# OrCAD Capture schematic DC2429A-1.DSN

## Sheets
1 PAGE1: size B
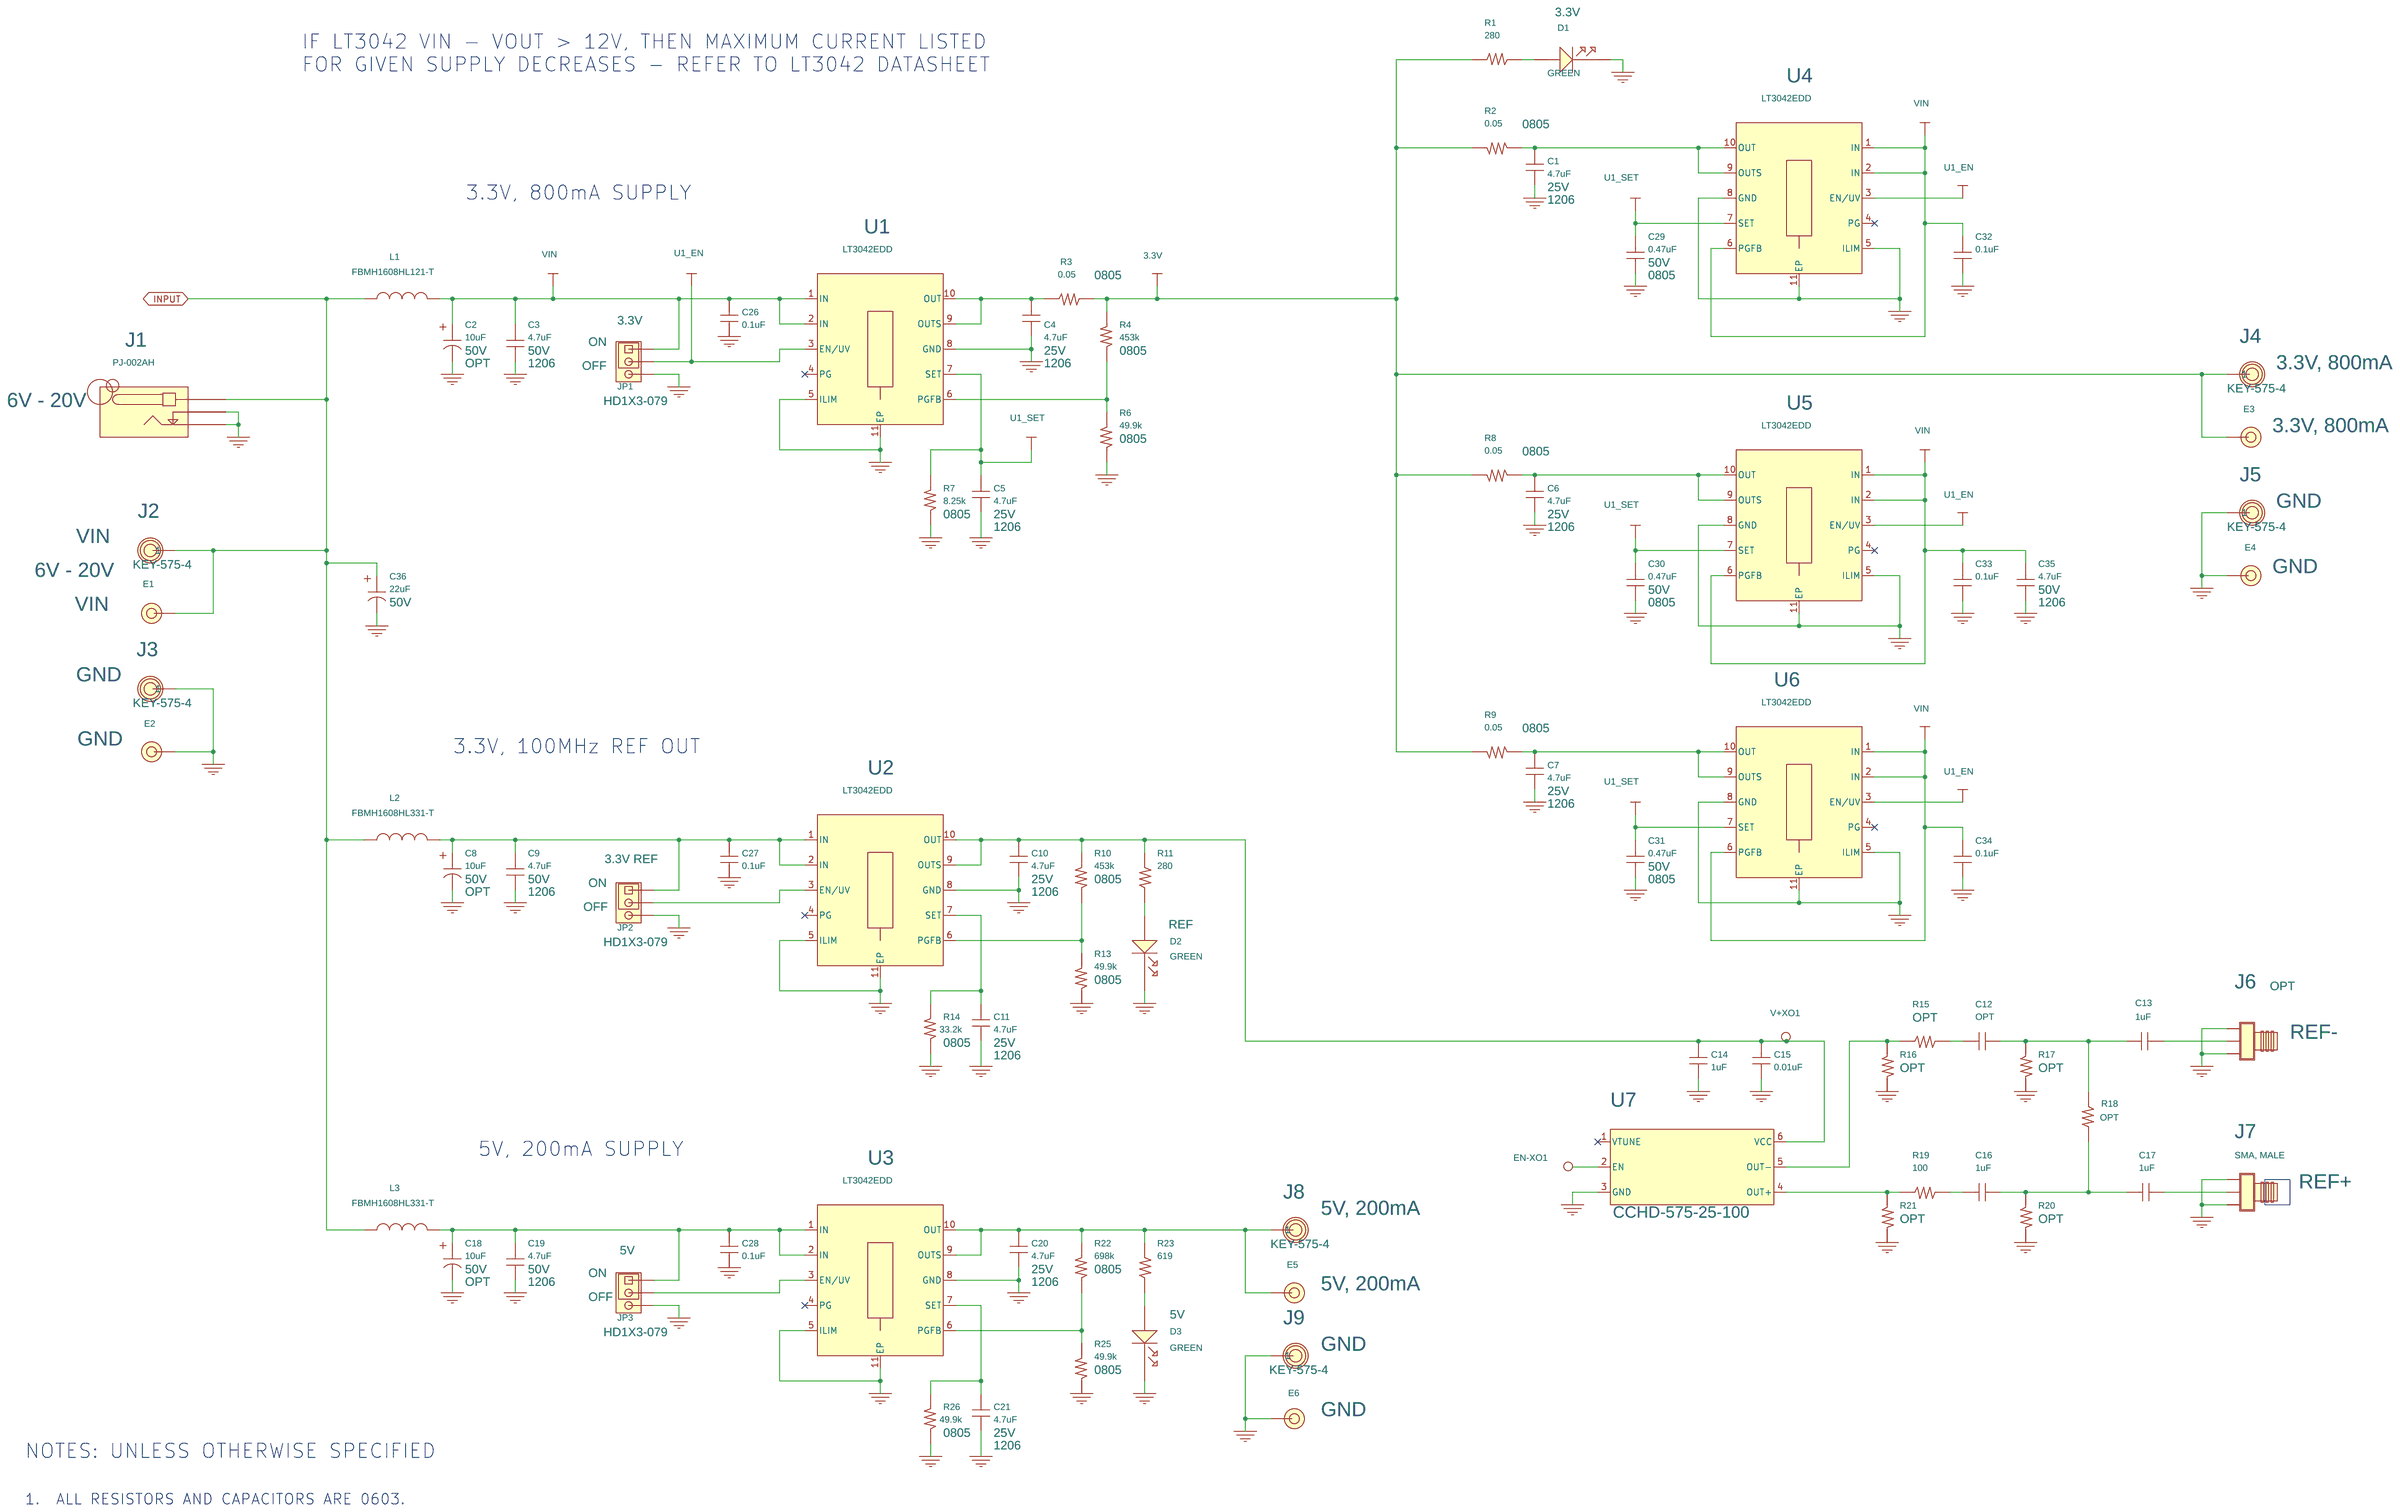
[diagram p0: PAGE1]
2 PAGE2: size B; title: PLL/VCO SUPPLY AND REFERENCE BOARD; rev: 1; note: DEMO CIRCUIT 2429A
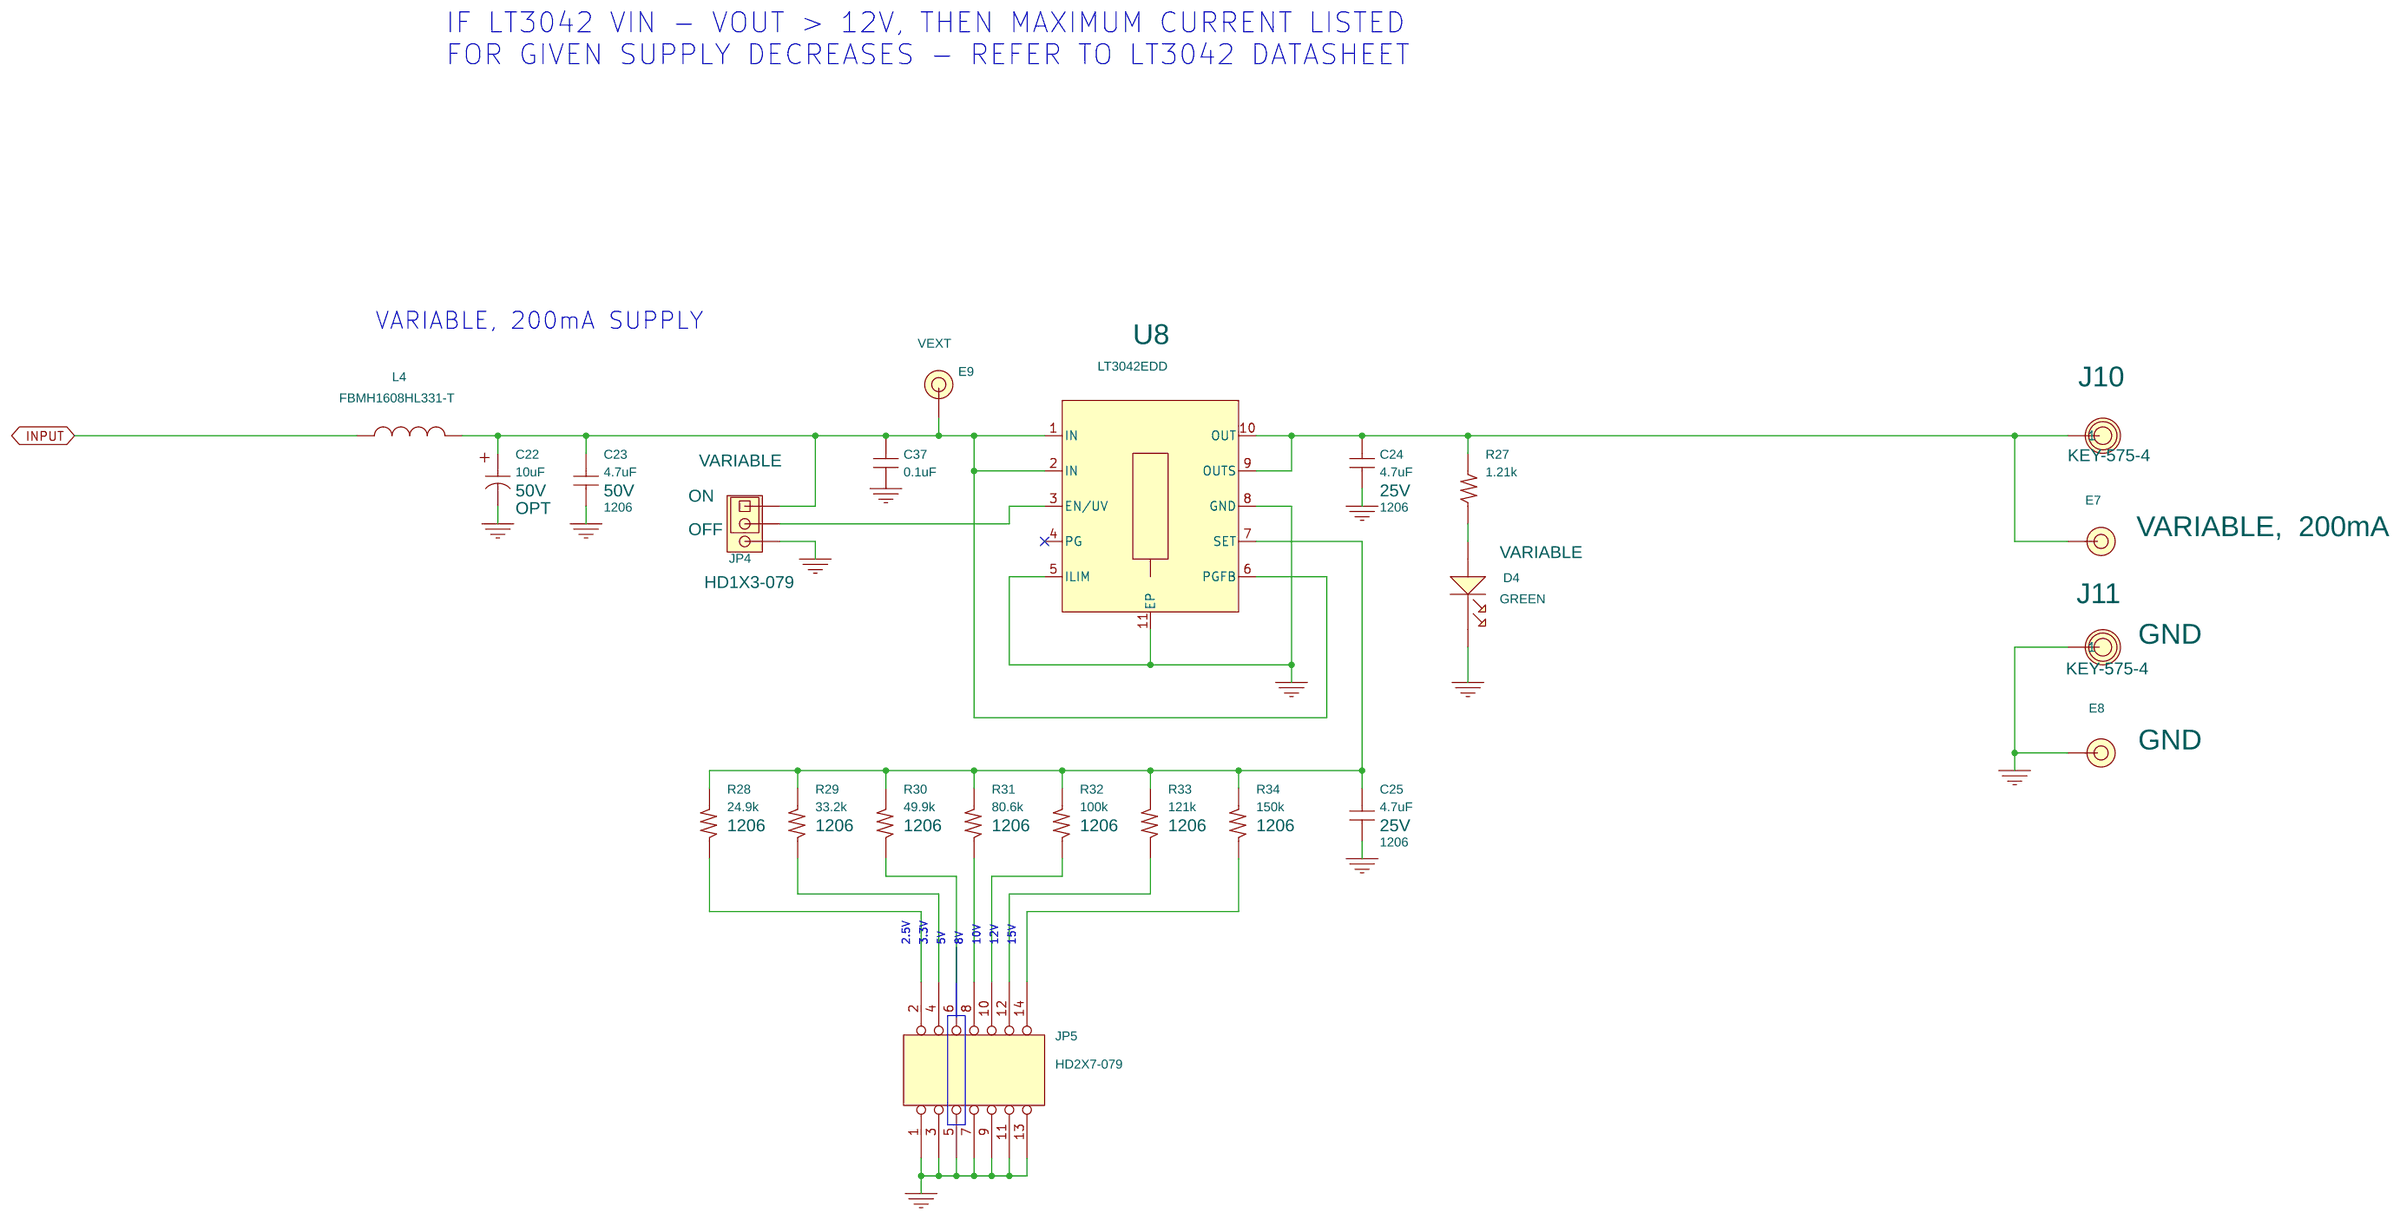
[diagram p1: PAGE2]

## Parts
sheet PAGE1
C1  4.7uF  [1206]
C2  10uF  [C-CE-BSS-5X5.4]
C3  4.7uF  [1206]
C4  4.7uF  [1206]
C5  4.7uF  [1206]
C6  4.7uF  [1206]
C7  4.7uF  [1206]
C8  10uF  [C-CE-BSS-5X5.4]
C9  4.7uF  [1206]
C10  4.7uF  [1206]
C11  4.7uF  [1206]
C12  C-0603  [0603]
C13  1uF  [0603]
C14  1uF  [0603]
C15  0.01uF  [0603]
C16  1uF  [0603]
C17  1uF  [0603]
C18  10uF  [C-CE-BSS-5X5.4]
C19  4.7uF  [1206]
C20  4.7uF  [1206]
C21  4.7uF  [1206]
C26  0.1uF  [0603]
C27  0.1uF  [0603]
C28  0.1uF  [0603]
C29  0.47uF  [0805]
C30  0.47uF  [0805]
C31  0.47uF  [0805]
C32  0.1uF  [0603]
C33  0.1uF  [0603]
C34  0.1uF  [0603]
C35  4.7uF  [1206]
C36  22uF  [C-CE-BSS-5X5.4]
D1  SML-012P8T  [LED-ROHM-SML-01]
D2  SML-012P8T  [LED-ROHM-SML-01]
D3  SML-012P8T  [LED-ROHM-SML-01]
E1  MILL-MAX-2308  [MILL-MAX-2308]
E2  MILL-MAX-2308  [MILL-MAX-2308]
E3  MILL-MAX-2308  [MILL-MAX-2308]
E4  MILL-MAX-2308  [MILL-MAX-2308]
E5  MILL-MAX-2308  [MILL-MAX-2308]
E6  MILL-MAX-2308  [MILL-MAX-2308]
EN-XO1  TESTPAD-SMD/050SQ  [TESTPAD-SMD/050SQ]
J1  PJ-002AH  [CON-CUI-PJ002AH]
J2  KEY-575-4  [KEY-575-4]
J3  KEY-575-4  [KEY-575-4]
J4  KEY-575-4  [KEY-575-4]
J5  KEY-575-4  [KEY-575-4]
J6  142-0701-851  [CON-SMA-R]
J7  142-0701-851  [CON-SMA-M-EFJOHNSON-142-0801-801]
J8  KEY-575-4  [KEY-575-4]
J9  KEY-575-4  [KEY-575-4]
JP1  HD1X3-079  [HD1X3-079]
JP2  HD1X3-079  [HD1X3-079]
JP3  HD1X3-079  [HD1X3-079]
L1  FBMH1608HL121-T  [0603]
L2  FBMH1608HL331-T  [0603]
L3  FBMH1608HL331-T  [0603]
R1  280  [0603]
R2  0.05  [0805]
R3  0.05  [0805]
R4  453k  [0805]
R6  49.9k  [0805]
R7  8.25k  [0805]
R8  0.05  [0805]
R9  0.05  [0805]
R10  453k  [0805]
R11  280  [0603]
R13  49.9k  [0805]
R14  33.2k  [0805]
R15  R-0603  [0603]
R16  R-0603  [0603]
R17  R-0603  [0603]
R18  R-0603  [0603]
R19  100  [0603]
R20  R-0603  [0603]
R21  R-0603  [0603]
R22  698k  [0805]
R23  619  [0603]
R25  49.9k  [0805]
R26  49.9k  [0805]
U1  LT3042EDD  [DFN10DD-3X3]
U2  LT3042EDD  [DFN10DD-3X3]
U3  LT3042EDD  [DFN10DD-3X3]
U4  LT3042EDD  [DFN10DD-3X3]
U5  LT3042EDD  [DFN10DD-3X3]
U6  LT3042EDD  [DFN10DD-3X3]
U7  CCHD-575-25-100  [Y-VCXO-NV13M08Y-DUAL]
V+XO1  TESTPAD-SMD/050SQ  [TESTPAD-SMD/050SQ]
sheet PAGE2
C22  10uF  [C-CE-BSS-5X5.4]
C23  4.7uF  [1206]
C24  4.7uF  [1206]
C25  4.7uF  [1206]
C37  0.1uF  [0603]
D4  SML-012P8T  [LED-ROHM-SML-01]
E7  MILL-MAX-2308  [MILL-MAX-2308]
E8  MILL-MAX-2308  [MILL-MAX-2308]
E9  MILL-MAX-2308  [MILL-MAX-2308]
J10  KEY-575-4  [KEY-575-4]
J11  KEY-575-4  [KEY-575-4]
JP4  HD1X3-079  [HD1X3-079]
JP5  HD2X7-079  [HD2X7-079]
L4  FBMH1608HL331-T  [0603]
R27  1.21k  [0603]
R28  24.9k  [1206]
R29  33.2k  [1206]
R30  49.9k  [1206]
R31  80.6k  [1206]
R32  100k  [1206]
R33  121k  [1206]
R34  150k  [1206]
U8  LT3042EDD  [DFN10DD-3X3]

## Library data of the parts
C1 C4-C7 C10 C11 C20 C21 C24 C25 = CAP-NP: 5th Part Field: 12065C104KATM; 7th Part Field: CAP.,; VOLTAGE: 25V
C2 C8 C18 C22 = CAP: OPT: OPT; Package Type: 7343; VOLTAGE: 50V
C3 C9 C19 C23 C29-C31 C35 = CAP-NP: 5th Part Field: 12065C104KATM; 7th Part Field: CAP.,; VOLTAGE: 50V
C12 = CAP-NP: 5th Part Field: 12065C104KATM; 7th Part Field: CAP.,; OPT: OPT
C13 C17 = CAP-NP
C14-C16 C26-C28 C32-C34 C37 = CAP-NP: 5th Part Field: 12065C104KATM; 7th Part Field: CAP.,
C36 = CAP: Package Type: 7343; VOLTAGE: 50V
D1 = LED_1: 10uH: <10uH>; 1st Part Field: GREEN; 2ND PART FIELD: 3.3V
D2 = LED_1: 10uH: <10uH>; 1st Part Field: GREEN; 2ND PART FIELD: REF
D3 = LED_1: 10uH: <10uH>; 1st Part Field: GREEN; 2ND PART FIELD: 5V
E1 = E_1: STATUS: 1.6V, 1.8V, 2.0V OR 2.5V @ 15A; label: VIN
E2 E4 E6 E8 = E_1: STATUS: 1.6V, 1.8V, 2.0V OR 2.5V @ 15A; label: GND
E3 = E_1: STATUS: 1.6V, 1.8V, 2.0V OR 2.5V @ 15A; label: 3.3V, 800mA
E5 = E_1: STATUS: 1.6V, 1.8V, 2.0V OR 2.5V @ 15A; label: 5V, 200mA
EN-XO1 V+XO1 = E-060-035
J1 = CONN_JACK_PWR,_2.1MM: 1ST PART FIELD: 6V - 20V
J2 = Keystone-575-4_0: 1st Part Field: VIN; 2ND PART FIELD: 6V - 20V; label: 5V
J3 J5 J9 J11 = Keystone-575-4_0: 9th Part Field: GND; label: 5V
J4 = Keystone-575-4_0: 9th Part Field: 3.3V, 800mA; label: 5V
J6 = SMA-CON-R: 1st Part Field: REF-; 2nd Part Field: IN; OPT: OPT
J7 = SMA-CON-R: 1st Part Field: REF+; 2nd Part Field: IN; PART: SMA, MALE
J8 = Keystone-575-4_0: 9th Part Field: 5V, 200mA; label: 5V
JP1 = HD1X3: 1st Part Field: 3.3V; 2nd Part Field: ON; 3rd Part Field: OFF
JP2 = HD1X3: 1st Part Field: 3.3V REF; 2nd Part Field: ON; 3rd Part Field: OFF
JP3 = HD1X3: 1st Part Field: 5V; 2nd Part Field: ON; 3rd Part Field: OFF
L1-L4 = IND: IND, 0805 TBD; COMPFIXED: CDR6D28MNNP-7R7NC; COMPGROUP: SUMIDA; Part Number: TBD
R1-R4 R6-R11 R13 R14 R19 R22 R23 R25-R34 = R
R15-R18 R20 R21 = R: OPT: OPT
U1-U6 U8 = LT3042EDD-DFN10DD-3X3
U7 = XXXXX4_2
D4 = LED_1: 10uH: <10uH>; 1st Part Field: GREEN; 2ND PART FIELD: VARIABLE
E7 = E_1: STATUS: 1.6V, 1.8V, 2.0V OR 2.5V @ 15A; label: VARIABLE,  200mA
E9 = E_1: STATUS: 1.6V, 1.8V, 2.0V OR 2.5V @ 15A; label: VEXT
J10 = Keystone-575-4_0: 1st Part Field: VARIABLE,  200mA; 9th Part Field: VEXT - VCO; label: 5V
JP4 = HD1X3: 1st Part Field: VARIABLE; 2nd Part Field: ON; 3rd Part Field: OFF
JP5 = HD2X7-079

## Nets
3.3V: E3.1(A) J4.1 R1.2 R2.2 R3.2 R4.2 R8.2 R9.2
GND: C1.1 C2.2 C3.1 C4.1 C5.1 C6.1 C7.1 C8.2 C9.1 C10.1 C11.1 C14.1 C15.1 C18.2 C19.1 C20.1 C21.1 C22.2 C23.1 C24.1 C25.1 C26.1 C27.1 C28.1 C29.1 C30.1 C31.1 C32.1 C33.1 C34.1 C35.1 C36.2 C37.1 D1.2 D2.2 D3.2 D4.2 E2.1(A) E4.1(A) E6.1(A) E8.1(A) J1.2 J1.3 J3.1 J5.1 J6.2(GND) J6.3(GND) J6.4(GND) J6.5(GND) J7.2(GND) J7.3(GND) J7.4(GND) J7.5(GND) J9.1 J11.1 JP1.3 JP2.3 JP3.3 JP4.3 JP5.1 JP5.3 JP5.5 JP5.7 JP5.9 JP5.11 JP5.13 R6.1 R7.1 R13.1 R14.1 R16.2 R17.2 R20.2 R21.2 R25.1 R26.1 U1.5(ILIM) U1.8(GND) U1.11(EP) U2.5(ILIM) U2.8(GND) U2.11(EP) U3.5(ILIM) U3.8(GND) U3.11(EP) U4.5(ILIM) U4.8(GND) U4.11(EP) U5.5(ILIM) U5.8(GND) U5.11(EP) U6.5(ILIM) U6.8(GND) U6.11(EP) U7.3(GND) U8.5(ILIM) U8.8(GND) U8.11(EP)
VIN: C2.1 C3.2 C26.2 C32.2 C33.2 C34.2 C35.2 JP1.1 L1.2 U1.1(IN) U1.2(IN) U4.1(IN) U4.2(IN) U4.6(PGFB) U5.1(IN) U5.2(IN) U5.6(PGFB) U6.1(IN) U6.2(IN) U6.6(PGFB)
INPUT: C36.1 E1.1(A) J1.1 J2.1 L1.1 L2.1 L3.1 L4.1
U1_EN: JP1.2 U1.3(EN/UV) U4.3(EN/UV) U5.3(EN/UV) U6.3(EN/UV)
U1_SET: C5.2 C29.2 C30.2 C31.2 R7.2 U1.7(SET) U4.7(SET) U5.7(SET) U6.7(SET)
N303825: C12.1 C13.1 R17.1 R18.1
N16693287: EN-XO1.1 U7.2(EN)
N16693428: R15.1 R16.1 U7.5(OUT-)
N16694043: R19.1 R21.1 U7.4(OUT+)
N16694842: C16.1 C17.2 R18.2 R20.1
N16707643: C10.2 C14.2 C15.2 R10.2 R11.2 U2.9(OUTS) U2.10(OUT) U7.6(VCC) V+XO1.1
N17820484: C12.2 R15.2
N17821277: C17.1 J7.1
N17821278: C13.2 J6.1
N17821353: C8.1 C9.2 C27.2 JP2.1 L2.2 U2.1(IN) U2.2(IN)
N17821668: JP2.2 U2.3(EN/UV)
N17823399: R10.1 R13.2 U2.6(PGFB)
N17825144: C18.1 C19.2 C28.2 JP3.1 L3.2 U3.1(IN) U3.2(IN)
N17825146: JP3.2 U3.3(EN/UV)
N17825182: C21.2 R26.2 U3.7(SET)
N17825213: R22.1 R25.2 U3.6(PGFB)
N17825258: C20.2 E5.1(A) J8.1 R22.2 R23.2 U3.9(OUTS) U3.10(OUT)
N17829005: C4.2 R3.1 U1.9(OUTS) U1.10(OUT)
N17829097: R4.1 R6.2 U1.6(PGFB)
N17830644: C1.2 R2.1 U4.9(OUTS) U4.10(OUT)
N17833327: D1.1 R1.1
N17833680: C6.2 R8.1 U5.9(OUTS) U5.10(OUT)
N17834019: C7.2 R9.1 U6.9(OUTS) U6.10(OUT)
N17838209: C22.1 C23.2 C37.2 E9.1(A) JP4.1 L4.2 U8.1(IN) U8.2(IN) U8.6(PGFB)
N17838211: C25.2 R28.2 R29.2 R30.2 R31.2 R32.2 R33.2 R34.2 U8.7(SET)
N17838234: JP4.2 U8.3(EN/UV)
N17838240: C24.2 E7.1(A) J10.1 R27.2 U8.9(OUTS) U8.10(OUT)
N17839773: JP5.14 R34.1
N17840121: JP5.12 R33.1
N17840348: JP5.8 R31.1
N17840380: JP5.10 R32.1
N17881882: C16.2 R19.2
N17885050: D2.1 R11.1
N17982847: C11.2 R14.2 U2.7(SET)
N17994993: D3.1 R23.1
N18063903: D4.1 R27.1
N18065906: JP5.6 R30.1
N18065915: JP5.4 R29.1
N18065924: JP5.2 R28.1

Not connected (* = marked no-connect by the designer): U1 4(PG)*; U2 4(PG)*; U3 4(PG)*; U4 4(PG)*; U5 4(PG)*; U6 4(PG)*; U7 1(VTUNE)*; U8 4(PG)*

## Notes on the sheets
sheet 1
- IF LT3042 VIN - VOUT > 12V, THEN MAXIMUM CURRENT LISTED
  FOR GIVEN SUPPLY DECREASES - REFER TO LT3042 DATASHEET
- 3.3V, 800mA SUPPLY
- 3.3V, 100MHz REF OUT
- 5V, 200mA SUPPLY
- NOTES: UNLESS OTHERWISE SPECIFIED
- 1.  ALL RESISTORS AND CAPACITORS ARE 0603.
sheet 2
- IF LT3042 VIN - VOUT > 12V, THEN MAXIMUM CURRENT LISTED
  FOR GIVEN SUPPLY DECREASES - REFER TO LT3042 DATASHEET
- VARIABLE, 200mA SUPPLY
- 2.5V
- 3.3V
- 5V
- 8V
- 10V
- 12V
- 15V
